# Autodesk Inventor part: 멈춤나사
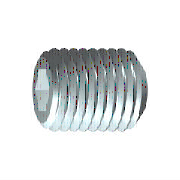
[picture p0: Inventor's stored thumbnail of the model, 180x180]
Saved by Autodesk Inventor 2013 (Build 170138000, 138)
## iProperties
IsCustomPart: 1
Company: 한국ATC센터
Created: 2009-02
Part Number: 멈춤나사
Material: 강, 연강
Description: 6각 소켓 머리 없는 멈춤 나사
Document SubType Name: Modeling
Standard: KS B 1028
Designer: KYOUNG IL JANG
Standards Organization: KS
Language: ko-KR
Size Designation: 납작점M3x6
Categories: <MemberInstance><Categories><Category DisplayName="조임쇠" InternalName="e4da775c-781d-43d5-af7c-5136215cf5a6" Mnemonic="FSTN"><Category DisplayName="볼트" InternalN
Density: 7.86 g/cm^3
Mass: 0.293227 g
Surface Area: 0.779766 cm^2
Volume: 0.0373062 cm^3
Vendor: CBT Solutions
Author: KYOUNG IL JANG
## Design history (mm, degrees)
sketch "스케치1"
  geometry: L1 (0, 0)-(3.5, 0); L2 (6, 0.866)-(6, 1.5); L3 (6, 1.5)-(0, 1.5); L4 (6, 0.866)-(4, 0.866); L5 (4, 0.866)-(3.5, 0); L6 (0, -0.3)-(0, 1.8) reference; L7 (0, 1.5)-(0, 0)
  constraints: 13 end point, 3 parallel, 1 collinear, 1 perpendicular, 1 point on line
  dimensions: "d0" = 2 distance of L2.start L4.end (= INTI); "d1" = 60 deg angle of L5 L1; "d2" = 3 diameter of L3 L1 (= NND); "d3" = 1.73205 diameter of L4 L1 (= 1.1547 x SW); "d5" = 6 distance from line of L2 L3.end (= NLG)
revolve "본체" sketch "스케치1" stored, may be unused: angle "d6" = 90 deg
sketch "스케치2"
  geometry: L1 (-0.433, 0.75)-(0.433, 0.75); L2 (0.433, 0.75)-(0.866, 0); L3 (0.866, 0)-(0.433, -0.75); L4 (0.433, -0.75)-(-0.433, -0.75); L5 (-0.433, -0.75)-(-0.866, 0); L6 (-0.866, 0)-(-0.433, 0.75); A1 r 0.866 centre (0, 0) between (-0.433, 0.75) and (0.433, 0.75) reference; 2 further points
  constraints: 12 end point, 2 point on circle, 1 coincident, 1 horizontal, 11 other
extrude "슬롯" join sketch "스케치2" taper "d9" = 0 deg; stored distance "d21" = 10
workaxis "Work Axis1"
workplane "Work Plane1"
body "Solid1"
chamfer "모따기1" distance "d7" = 0.30673 (= -0.5 x GD1 + 0.5 x NND); stored, may be unused: angle "d8" = 45 deg (= FAWI), second distance "d29" = 0.30673 (= -0.5 x GD1 + 0.5 x NND)
feature "스레드" dims "d11" = 6 (= NLG), "d12" = 0
chamfer "모따기2" distance "d13" = 0.30673 (= -0.5 x GD1 + 0.5 x NND); stored, may be unused: angle "d14" = 45 deg (= FAWI), second distance "d30" = 0.30673 (= -0.5 x GD1 + 0.5 x NND)
other parameters: "NND" = 3 [user parameter; used in 5 equation terms], "NLG" = 6 [user parameter; used in 2 equation terms], "INTI" = 2 [user parameter; used in 1 equation term], "FAWI" = 45 deg [user parameter; used in 2 equation terms], "SW" = 1.5 [user parameter; used in 2 equation terms], "GD1" = 2.38655 (= THREADDIA - 1.2269 x PTC) [user parameter; used in 4 equation terms], "d4" = 0, "FAWI1" = 45 deg [user parameter], "d15" = 0, "d31" = 0, "GUL" = 0.30673 (= 0.61345 x PTC) [user parameter], "SPD" = 2 [user parameter], "TOA" = 30 deg [user parameter], "THREADDIA" = 3 [user parameter; used in 1 equation term], "PTC" = 0.5 [user parameter; used in 4 equation terms], "GAL" = 0.30673 (= 0.61345 x PTC) [user parameter], "E0" = 1.7325 (= 1.155 x SW) [user parameter]
